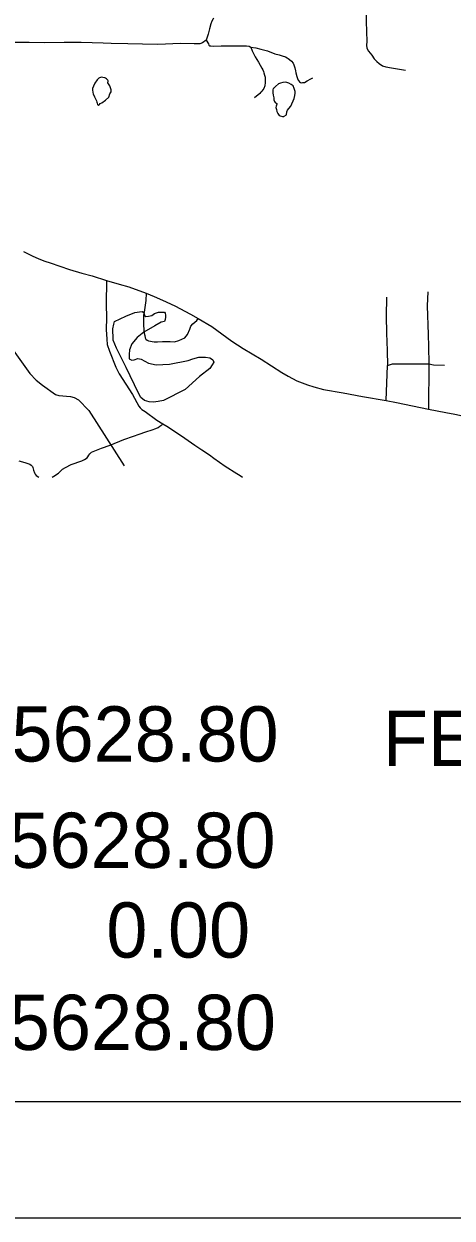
# Model space of a CAD drawing. Extents: x 61396 to 64680, y 55472 to 57605.
# Drawn here: x 63042.5 to 63187.7, y 55472.1 to 55877.6 of the extents above; entities that cross this region are included whole.
import ezdxf

# ---------------------------------------------------------------- set-up
doc = ezdxf.new("R2010")
doc.units = 0
for name, color, linetype in [('31', 7, 'Continuous'), ('32', 7, 'Continuous'), ('35', 7, 'Continuous'), ('45', 7, 'Continuous'), ('Default', 7, 'Continuous'), ('R_Border Notes', 7, 'Continuous'), ('R_No Plot', 7, 'Continuous')]:
    doc.layers.add(name, color=color, linetype=linetype)

msp = doc.modelspace()

# ---------------------------------------------------------------- linework, layer by layer
at = {"layer": '31'}
for p, q in [((63165.33, 55749.79), (63165.81, 55761.67)), ((63179.86, 55762.17), (63179.7, 55746.85))]:
    msp.add_line(p, q, dxfattribs=at)
for points in [[(63106.87, 55879.63), (63106.63, 55879.34), (63106.18, 55878.56), (63105.89, 55877.69), (63105.4, 55876.01), (63104.98, 55874.2), (63104.28, 55872.11)], [(63104.28, 55872.11), (63103.07, 55871.16), (63102.16, 55870.9), (63100.23, 55870.84), (63095.61, 55870.97), (63087.86, 55870.68), (63082.67, 55870.71), (63077.77, 55870.9), (63072.07, 55871), (63069.38, 55871.09), (63061.92, 55871.31), (63056.19, 55871.31), (63049.61, 55871.25), (63044.26, 55871.28), (63023.48, 55871.32)], [(63042.29, 55800.37), (63045.23, 55798.83), (63047.54, 55797.89), (63049.54, 55797.13), (63051.33, 55796.53), (63057.95, 55794.22), (63062.17, 55792.99), (63065.58, 55792.05), (63070.53, 55790.53)], [(63070.53, 55790.53), (63074.79, 55789.3), (63078.1, 55788.35), (63083.92, 55786.2)], [(63083.92, 55786.2), (63083.81, 55783.74), (63083.3, 55779.81), (63083.09, 55778.85), (63083.06, 55775.26), (63083.33, 55772.63), (63083.47, 55771.78), (63083.64, 55771.06), (63083.84, 55770.62), (63084.32, 55770.24), (63084.77, 55770), (63086.68, 55769.69), (63087.84, 55769.66), (63089.52, 55769.76), (63092.11, 55769.76), (63093.58, 55769.69), (63095.02, 55770.1), (63097.03, 55771.06), (63097.99, 55772.15), (63098.74, 55773.93), (63099.15, 55774.96), (63099.77, 55775.77), (63101.13, 55776.97), (63101.6, 55777.64)], [(63083.92, 55786.2), (63086.68, 55785.03), (63089.45, 55783.84), (63093.69, 55781.86), (63098.98, 55779.12), (63101.6, 55777.64)], [(63165.44, 55784.9), (63165.33, 55778.45), (63165.49, 55772.61), (63165.66, 55766.77), (63165.81, 55761.67)], [(63179.51, 55786.68), (63179.29, 55781.96), (63179.57, 55772.17), (63179.73, 55768.05), (63179.86, 55762.17)], [(63101.6, 55777.64), (63106.19, 55774.85), (63113.03, 55769.86), (63116.82, 55767.4), (63122.97, 55763.82), (63130.01, 55759.24), (63132.13, 55758.04), (63135.07, 55756.4), (63138.72, 55755.11), (63140.81, 55754.35), (63144.15, 55753.53), (63150.76, 55752.34), (63157.32, 55751.17), (63165.33, 55749.79)], [(63165.81, 55761.67), (63167.52, 55762.17), (63169.57, 55762.17), (63179.86, 55762.17)], [(63179.86, 55762.17), (63181.48, 55761.93), (63185.2, 55761.76)], [(63165.33, 55749.79), (63168.92, 55749.03), (63179.7, 55746.85)], [(63179.7, 55746.85), (63185.64, 55745.72), (63188.69, 55745.18), (63191.31, 55744.61), (63195.16, 55743.69)]]:
    msp.add_lwpolyline(points, dxfattribs=at)
at = {"layer": '32'}
for points in [[(63158.91, 55890.3), (63158.9, 55890.03), (63158.85, 55885.71), (63158.62, 55881.02), (63158.62, 55878.44), (63158.85, 55871.68), (63158.75, 55870.38), (63158.83, 55869.42), (63159.38, 55868.38), (63160.5, 55867.05), (63161.33, 55865.76), (63162.16, 55864.84), (63163.04, 55864.14), (63164.08, 55863.35), (63165.28, 55863.05), (63167.16, 55862.72), (63171.99, 55861.97)], [(63040.76, 55729.27), (63042.76, 55728.76), (63043.5, 55728.52), (63044.16, 55728.31), (63044.48, 55728.16), (63044.93, 55727.8), (63045.39, 55727.38), (63045.56, 55726.99), (63045.74, 55726.1), (63046.03, 55725.25), (63046.27, 55724.72), (63046.67, 55724.27), (63047.55, 55723.76)], [(63052.07, 55723.76), (63052.6, 55724.06), (63054.21, 55725.14), (63055.61, 55726.48), (63056.55, 55727.07), (63058.48, 55728.06), (63062.18, 55729.27)]]:
    msp.add_lwpolyline(points, dxfattribs=at)
at = {"layer": '35'}
msp.add_lwpolyline([(63068.72, 55859.51), (63067.92, 55859.25), (63067.3, 55858.63), (63066.53, 55857.47), (63066.09, 55856.55), (63065.77, 55855.68), (63065.73, 55855.28), (63065.91, 55854.4), (63065.98, 55853.86), (63066.39, 55852.91), (63067.08, 55851.52), (63067.26, 55851.08), (63067.33, 55850.68), (63067.41, 55850.28), (63067.63, 55850.03), (63067.77, 55849.95), (63067.95, 55849.99), (63068.14, 55850.25), (63068.32, 55850.57), (63068.9, 55850.87), (63070.18, 55851.7), (63071.24, 55852.8), (63071.64, 55853.89), (63072.08, 55854.59), (63072.11, 55855.28), (63071.89, 55855.97), (63071.64, 55856.63), (63071.35, 55856.99), (63070.98, 55857.58), (63070.98, 55857.83), (63071.09, 55858.05), (63071.02, 55858.31), (63070.98, 55858.56), (63070.54, 55858.96), (63070.14, 55859.22), (63069.89, 55859.33), (63069.27, 55859.47)], close=True, dxfattribs=at)
for points in [[(63131.53, 55846.81), (63131.71, 55847.8), (63131.86, 55848.36), (63132.32, 55848.92), (63133.03, 55849.67), (63134.2, 55852.35), (63134.34, 55853.34), (63134.48, 55854.09), (63134.48, 55854.7), (63134.2, 55855.73), (63133.87, 55856.57), (63133.17, 55857.09), (63132.32, 55857.51), (63131.29, 55857.84), (63130.35, 55857.79), (63129.56, 55857.51), (63128.8, 55857.32), (63127.87, 55856.39), (63127.3, 55855.87), (63127.07, 55855.68), (63126.97, 55855.26), (63126.93, 55854.93), (63126.88, 55854.51), (63126.93, 55854.18), (63127.07, 55853.43), (63127.3, 55852.58), (63127.3, 55851.83), (63127.49, 55851.32), (63127.72, 55850.99), (63127.96, 55850.89), (63128.24, 55850.66), (63128.24, 55850.33), (63128.19, 55850.1), (63128.1, 55849.67), (63127.96, 55849.21), (63128.19, 55848.55), (63128.29, 55847.94), (63128.62, 55847.19), (63129.04, 55846.58), (63129.41, 55846.39), (63130.26, 55846.25), (63130.63, 55846.25), (63130.82, 55846.34), (63131.53, 55846.81)], [(63098.17, 55763.35), (63099.78, 55763.96), (63101.84, 55764.44), (63104.14, 55764.44), (63105.53, 55764.26), (63106.08, 55763.96), (63106.62, 55763.53), (63106.87, 55762.74), (63106.38, 55761.84), (63105.59, 55760.68), (63102.02, 55757.96), (63097.17, 55753.48), (63089.84, 55749.78), (63088.08, 55749.42), (63086.45, 55749.17), (63084.99, 55749.3), (63083.36, 55749.78), (63082.15, 55750.81), (63081.3, 55752.26), (63077.12, 55760.93), (63073.91, 55767.59), (63072.75, 55770.26), (63072.81, 55771.71), (63072.69, 55772.92), (63072.69, 55774.13), (63072.94, 55775.65), (63073.24, 55776.56), (63077, 55778.37), (63080.09, 55779.65), (63081.66, 55779.89), (63082.57, 55780.01), (63083.15, 55779.7), (63083.42, 55778.62), (63083.84, 55778.31), (63084.75, 55778.37), (63085.9, 55778.68), (63086.75, 55779.28), (63088.14, 55779.71), (63089.23, 55779.77), (63090.14, 55779.71), (63090.39, 55779.46), (63090.51, 55778.74), (63090.51, 55778.01), (63090.45, 55777.28), (63090.2, 55776.62), (63089.05, 55776.31), (63086.87, 55775.1), (63083.2, 55773.01), (63080.87, 55771.1), (63079.12, 55768.98), (63078.27, 55766.92), (63078.21, 55765.35), (63078.21, 55763.96), (63079.06, 55763.47), (63079.9, 55763.53), (63081.18, 55764.08), (63082.21, 55763.83), (63084.75, 55762.44), (63087.36, 55761.9), (63091.84, 55762.08), (63098.17, 55763.35)]]:
    msp.add_lwpolyline(points, dxfattribs=at)
at = {"layer": '45'}
for points in [[(63104.28, 55872.11), (63105.05, 55870.9), (63105.27, 55870.44), (63105.57, 55870.2), (63105.92, 55870.16), (63106.71, 55870.09), (63109.41, 55870.2), (63113.08, 55870.24), (63117.94, 55870.22), (63118.85, 55870.1), (63119.44, 55869.77)], [(63119.44, 55869.77), (63121.18, 55869.53), (63122.82, 55869.11), (63125.12, 55868.47), (63127.65, 55867.52), (63129.05, 55867.13), (63129.46, 55867.07), (63130.09, 55866.85), (63131.18, 55866.48), (63131.82, 55866.17), (63132.15, 55865.92), (63132.62, 55865.53), (63133.22, 55864.93), (63133.8, 55864.26), (63134.08, 55863.72), (63134.35, 55862.67), (63134.64, 55861.73), (63134.78, 55860.99), (63135.03, 55859.78), (63135.28, 55859.08), (63135.52, 55858.56), (63135.75, 55858.27), (63136, 55858.01), (63136.37, 55857.76), (63136.8, 55857.68), (63137.15, 55857.7), (63137.64, 55857.76), (63138.52, 55858.26), (63139.77, 55858.99), (63140.5, 55859.35)], [(63119.44, 55869.77), (63119.9, 55868.49), (63120.52, 55867.31), (63120.99, 55866.47), (63121.54, 55865.51), (63122.11, 55864.65), (63123.23, 55862.63), (63123.48, 55862.08), (63123.72, 55861.53), (63123.89, 55861.04), (63124.15, 55860.26), (63124.28, 55859.53), (63124.32, 55859), (63124.32, 55858.42), (63124.32, 55857.79), (63124.17, 55856.56), (63123.87, 55855.73), (63123.56, 55855.28), (63123.17, 55854.77), (63122.91, 55854.42), (63122.52, 55854.03), (63120.68, 55852.56)], [(63070.53, 55790.53), (63070.42, 55782.51), (63070.47, 55777.8), (63070.37, 55773.87), (63070.58, 55770.62), (63070.74, 55768.73), (63071.57, 55766.53), (63073.62, 55761.08), (63074.77, 55758.78), (63079.28, 55751.76), (63081.52, 55747.86), (63081.95, 55747.22), (63082.46, 55746.76), (63083.61, 55745.99), (63087.63, 55743.08), (63089.65, 55741.79)], [(63062.18, 55729.27), (63063.01, 55729.71), (63063.9, 55730.27), (63064.16, 55730.61), (63064.52, 55731.23), (63064.85, 55731.68), (63065.45, 55732.21), (63068.84, 55733.59), (63071.79, 55734.62), (63076.33, 55736.48), (63079.67, 55737.67), (63081.62, 55738.35), (63083.8, 55739.11), (63086.03, 55739.81), (63087.24, 55740.29), (63087.97, 55740.64), (63088.61, 55741.07), (63089.31, 55741.53), (63089.65, 55741.79)], [(63089.65, 55741.79), (63090.92, 55741.1), (63093.24, 55739.54), (63097.08, 55736.98), (63100.47, 55734.64), (63102.83, 55733.03), (63105.47, 55731.26), (63106.92, 55730.15), (63110.79, 55727.52), (63114.69, 55724.99), (63115.88, 55724.29), (63116.65, 55723.76)]]:
    msp.add_lwpolyline(points, dxfattribs=at)
at = {"layer": 'Default'}
msp.add_line((64633.61, 55511.58), (61471.8, 55511.58), dxfattribs=at)
msp.add_lwpolyline([(63033.98, 55773.54), (63044.48, 55758.95), (63046.69, 55756.71), (63048.73, 55755), (63053.15, 55751.81), (63054.31, 55751.42), (63058.23, 55751.15), (63059.55, 55750.84), (63061.04, 55749.96), (63064.45, 55746.37), (63076.44, 55727.58)], dxfattribs=at)
at = {"layer": 'R_No Plot'}
msp.add_lwpolyline([(61396.28, 57605.48), (64679.67, 57605.48), (64679.67, 55472.15), (61396.28, 55472.15)], close=True, dxfattribs=at)

# ---------------------------------------------------------------- texts
at = {"layer": 'Default'}
msp.add_text('FEET  OR   2.960', height=18.75, dxfattribs=at).set_placement((63164.23, 55625.66))
at = {"layer": 'R_Border Notes'}
for s, p in [('15628.80', (63024.3, 55627.18)), ('15628.80', (63023.28, 55591.08)), ('0.00', (63070.43, 55560.6)), ('15628.80', (63023.4, 55529.25))]:
    msp.add_text(s, height=18.75, dxfattribs=at).set_placement(p)

doc.saveas('drawing.dxf')
